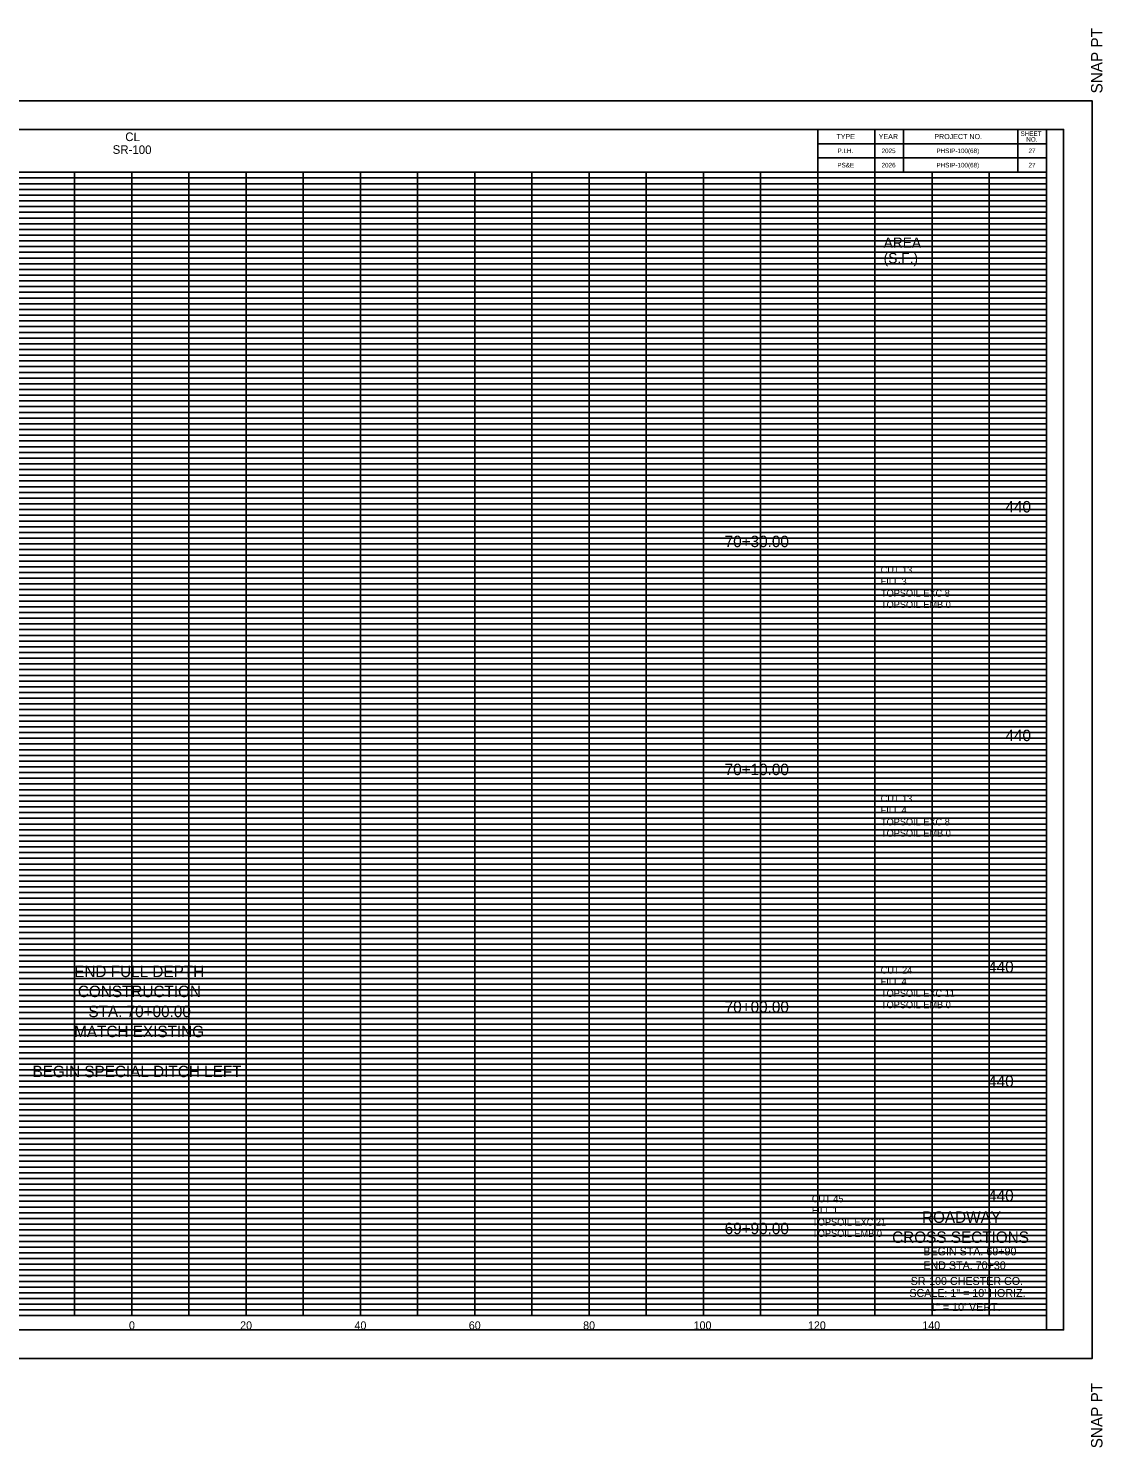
# Model space of a CAD drawing. Extents: x 37 to 1710, y 707 to 2305.
# Drawn here: x 1521.9 to 1709.8, y 1516.9 to 1765.2 of the extents above; entities that cross this region are included whole.
import ezdxf

# ---------------------------------------------------------------- set-up
doc = ezdxf.new("R2010")
doc.units = 0
for name, color, linetype in [('DESIGN - DRAINAGE - Special Ditch Width Text', 7, 'Continuous'), ('DESIGN - SCRATCH - User 1', 7, 'Continuous'), ('DESIGN - SHEET - Corner Text', 7, 'Continuous'), ('DESIGN - SHEET - Light Grid', 7, 'Continuous'), ('DESIGN - SHEET - Linework', 7, 'Continuous'), ('DESIGN - SHEET - Plot Shape', 7, 'Continuous'), ('DESIGN - TYPICAL - Text', 7, 'Continuous')]:
    doc.layers.add(name, color=color, linetype=linetype)

msp = doc.modelspace()

# ---------------------------------------------------------------- linework, layer by layer
at = {"layer": 'DESIGN - SCRATCH - User 1'}
for p, q in [((1665, 1743.75), (1665, 1743.75)), ((1672.5, 1743.75), (1672.5, 1743.75)), ((1685, 1743.75), (1685, 1743.75)), ((1697.5, 1743.75), (1697.5, 1743.75)), ((1665, 1741.25), (1665, 1741.25)), ((1672.5, 1741.25), (1672.5, 1741.25)), ((1685, 1741.25), (1685, 1741.25)), ((1697.5, 1741.25), (1697.5, 1741.25))]:
    msp.add_line(p, q, dxfattribs=at)
at = {"layer": 'DESIGN - SHEET - Light Grid'}
for p, q in [((1380, 1739), (1700, 1739)), ((1380, 1738), (1700, 1738)), ((1380, 1737), (1700, 1737)), ((1380, 1736), (1700, 1736)), ((1380, 1735), (1700, 1735)), ((1380, 1734), (1700, 1734)), ((1380, 1733), (1700, 1733)), ((1380, 1732), (1700, 1732)), ((1380, 1731), (1700, 1731)), ((1380, 1729), (1700, 1729)), ((1380, 1728), (1700, 1728)), ((1380, 1727), (1700, 1727)), ((1380, 1726), (1700, 1726)), ((1380, 1725), (1700, 1725)), ((1380, 1724), (1700, 1724)), ((1380, 1723), (1700, 1723)), ((1380, 1722), (1700, 1722)), ((1380, 1721), (1700, 1721)), ((1380, 1719), (1700, 1719)), ((1380, 1718), (1700, 1718)), ((1380, 1717), (1700, 1717)), ((1380, 1716), (1700, 1716)), ((1380, 1715), (1700, 1715)), ((1380, 1714), (1700, 1714)), ((1380, 1713), (1700, 1713)), ((1380, 1712), (1700, 1712)), ((1380, 1711), (1700, 1711)), ((1380, 1709), (1700, 1709)), ((1380, 1708), (1700, 1708)), ((1380, 1707), (1700, 1707)), ((1380, 1706), (1700, 1706)), ((1380, 1705), (1700, 1705)), ((1380, 1704), (1700, 1704)), ((1380, 1703), (1700, 1703)), ((1380, 1702), (1700, 1702)), ((1380, 1701), (1700, 1701)), ((1380, 1699), (1700, 1699)), ((1380, 1698), (1700, 1698)), ((1380, 1697), (1700, 1697)), ((1380, 1696), (1700, 1696)), ((1380, 1695), (1700, 1695)), ((1380, 1694), (1700, 1694)), ((1380, 1693), (1700, 1693)), ((1380, 1692), (1700, 1692)), ((1380, 1691), (1700, 1691)), ((1380, 1689), (1700, 1689)), ((1380, 1688), (1700, 1688)), ((1380, 1687), (1700, 1687)), ((1380, 1686), (1700, 1686)), ((1380, 1685), (1700, 1685)), ((1380, 1684), (1700, 1684)), ((1380, 1683), (1700, 1683)), ((1380, 1682), (1700, 1682)), ((1380, 1681), (1700, 1681)), ((1380, 1679), (1700, 1679)), ((1380, 1678), (1700, 1678)), ((1380, 1677), (1700, 1677)), ((1380, 1676), (1700, 1676)), ((1380, 1675), (1700, 1675)), ((1380, 1674), (1700, 1674)), ((1380, 1673), (1700, 1673)), ((1380, 1672), (1700, 1672)), ((1380, 1671), (1700, 1671)), ((1380, 1669), (1700, 1669)), ((1380, 1668), (1700, 1668)), ((1380, 1667), (1700, 1667)), ((1380, 1666), (1700, 1666)), ((1380, 1665), (1700, 1665)), ((1380, 1664), (1700, 1664)), ((1380, 1663), (1700, 1663)), ((1380, 1662), (1700, 1662)), ((1380, 1661), (1700, 1661)), ((1380, 1659), (1700, 1659)), ((1380, 1658), (1700, 1658)), ((1380, 1657), (1700, 1657)), ((1380, 1656), (1700, 1656)), ((1380, 1655), (1700, 1655)), ((1380, 1654), (1700, 1654)), ((1380, 1653), (1700, 1653)), ((1380, 1652), (1700, 1652)), ((1380, 1651), (1700, 1651)), ((1380, 1649), (1700, 1649)), ((1380, 1648), (1700, 1648)), ((1380, 1647), (1700, 1647)), ((1380, 1646), (1700, 1646)), ((1380, 1645), (1700, 1645)), ((1380, 1644), (1700, 1644)), ((1380, 1643), (1700, 1643)), ((1380, 1642), (1700, 1642)), ((1380, 1641), (1700, 1641)), ((1380, 1639), (1700, 1639)), ((1380, 1638), (1700, 1638)), ((1380, 1637), (1700, 1637)), ((1380, 1636), (1700, 1636)), ((1380, 1635), (1700, 1635)), ((1380, 1634), (1700, 1634)), ((1380, 1633), (1700, 1633)), ((1380, 1632), (1700, 1632)), ((1380, 1631), (1700, 1631)), ((1380, 1629), (1700, 1629)), ((1380, 1628), (1700, 1628)), ((1380, 1627), (1700, 1627)), ((1380, 1626), (1700, 1626)), ((1380, 1625), (1700, 1625)), ((1380, 1624), (1700, 1624)), ((1380, 1623), (1700, 1623)), ((1380, 1622), (1700, 1622)), ((1380, 1621), (1700, 1621)), ((1380, 1619), (1700, 1619)), ((1380, 1618), (1700, 1618)), ((1380, 1617), (1700, 1617)), ((1380, 1616), (1700, 1616)), ((1380, 1615), (1700, 1615)), ((1380, 1614), (1700, 1614)), ((1380, 1613), (1700, 1613)), ((1380, 1612), (1700, 1612)), ((1380, 1611), (1700, 1611)), ((1380, 1609), (1700, 1609)), ((1380, 1608), (1700, 1608)), ((1380, 1607), (1700, 1607)), ((1380, 1606), (1700, 1606)), ((1380, 1605), (1700, 1605)), ((1380, 1604), (1700, 1604)), ((1380, 1603), (1700, 1603)), ((1380, 1602), (1700, 1602)), ((1380, 1601), (1700, 1601)), ((1380, 1599), (1700, 1599)), ((1380, 1598), (1700, 1598)), ((1380, 1597), (1700, 1597)), ((1380, 1596), (1700, 1596)), ((1380, 1595), (1700, 1595)), ((1380, 1594), (1700, 1594)), ((1380, 1593), (1700, 1593)), ((1380, 1592), (1700, 1592)), ((1380, 1591), (1700, 1591)), ((1380, 1589), (1700, 1589)), ((1380, 1588), (1700, 1588)), ((1380, 1587), (1700, 1587)), ((1380, 1586), (1700, 1586)), ((1380, 1585), (1700, 1585)), ((1380, 1584), (1700, 1584)), ((1380, 1583), (1700, 1583)), ((1380, 1582), (1700, 1582)), ((1380, 1581), (1700, 1581)), ((1380, 1579), (1700, 1579)), ((1380, 1578), (1700, 1578)), ((1380, 1577), (1700, 1577)), ((1380, 1576), (1700, 1576)), ((1380, 1575), (1700, 1575)), ((1380, 1574), (1700, 1574)), ((1380, 1573), (1700, 1573)), ((1380, 1572), (1700, 1572)), ((1380, 1571), (1700, 1571)), ((1380, 1569), (1700, 1569)), ((1380, 1568), (1700, 1568)), ((1380, 1567), (1700, 1567)), ((1380, 1566), (1700, 1566)), ((1380, 1565), (1700, 1565)), ((1380, 1564), (1700, 1564)), ((1380, 1563), (1700, 1563)), ((1380, 1562), (1700, 1562)), ((1380, 1561), (1700, 1561)), ((1380, 1559), (1700, 1559)), ((1380, 1558), (1700, 1558)), ((1380, 1557), (1700, 1557)), ((1380, 1556), (1700, 1556)), ((1380, 1555), (1700, 1555)), ((1380, 1554), (1700, 1554)), ((1380, 1553), (1700, 1553)), ((1380, 1552), (1700, 1552)), ((1380, 1551), (1700, 1551)), ((1380, 1549), (1700, 1549)), ((1380, 1548), (1700, 1548)), ((1380, 1547), (1700, 1547)), ((1380, 1546), (1700, 1546)), ((1380, 1545), (1700, 1545)), ((1380, 1544), (1700, 1544)), ((1380, 1543), (1700, 1543)), ((1380, 1542), (1700, 1542)), ((1380, 1541), (1700, 1541))]:
    msp.add_line(p, q, dxfattribs=at)
at = {"layer": 'DESIGN - SHEET - Linework'}
for p, q in [((1700, 1747.5), (1660, 1747.5)), ((1660, 1740), (1660, 1747.5)), ((1670, 1740), (1670, 1747.5)), ((1675, 1740), (1675, 1747.5)), ((1695, 1740), (1695, 1747.5)), ((1700, 1740), (1700, 1747.5)), ((1700, 1745), (1660, 1745)), ((1700, 1742.5), (1660, 1742.5)), ((1380, 1740), (1700, 1740)), ((1530, 1540), (1530, 1740)), ((1540, 1540), (1540, 1740)), ((1550, 1540), (1550, 1740)), ((1560, 1540), (1560, 1740)), ((1570, 1540), (1570, 1740)), ((1580, 1540), (1580, 1740)), ((1590, 1540), (1590, 1740)), ((1600, 1540), (1600, 1740)), ((1610, 1540), (1610, 1740)), ((1620, 1540), (1620, 1740)), ((1630, 1540), (1630, 1740)), ((1640, 1540), (1640, 1740)), ((1650, 1540), (1650, 1740)), ((1660, 1540), (1660, 1740)), ((1670, 1540), (1670, 1740)), ((1680, 1540), (1680, 1740)), ((1690, 1540), (1690, 1740)), ((1380, 1730), (1700, 1730)), ((1380, 1720), (1700, 1720)), ((1380, 1710), (1700, 1710)), ((1380, 1700), (1700, 1700)), ((1380, 1690), (1700, 1690)), ((1380, 1680), (1700, 1680)), ((1380, 1670), (1700, 1670)), ((1380, 1660), (1700, 1660)), ((1380, 1650), (1700, 1650)), ((1380, 1640), (1700, 1640)), ((1380, 1630), (1700, 1630)), ((1380, 1620), (1700, 1620)), ((1380, 1610), (1700, 1610)), ((1380, 1600), (1700, 1600)), ((1380, 1590), (1700, 1590)), ((1380, 1580), (1700, 1580)), ((1380, 1570), (1700, 1570)), ((1380, 1560), (1700, 1560)), ((1380, 1550), (1700, 1550)), ((1380, 1540), (1700, 1540))]:
    msp.add_line(p, q, dxfattribs=at)
for points in [[(1368, 1752.5), (1708, 1752.5), (1708, 1532.5), (1368, 1532.5)], [(1380, 1747.5), (1700, 1747.5), (1700, 1537.5), (1380, 1537.5)]]:
    msp.add_lwpolyline(points, close=True, dxfattribs=at)
at = {"layer": 'DESIGN - SHEET - Plot Shape'}
msp.add_lwpolyline([(1373, 1747.5), (1703, 1747.5), (1703, 1537.5), (1373, 1537.5)], close=True, dxfattribs=at)

# ---------------------------------------------------------------- texts
at = {"layer": 'DESIGN - DRAINAGE - Special Ditch Width Text'}
for s, p in [('CL', (1538.85, 1745.46)), ('SR-100', (1536.64, 1743.23))]:
    msp.add_text(s, height=1.5, rotation=359.6675, dxfattribs=at).set_placement(p)
at = {"layer": 'DESIGN - SHEET - Corner Text'}
for s, p in [('  SNAP PT', (1709.8, 1752.3)), ('SNAP PT  ', (1709.8, 1516.8))]:
    msp.add_text(s, height=2, rotation=90, dxfattribs=at).set_placement(p)
for s, height, p in [('P.I.H.', 0.8, (1663.45, 1743.35)), ('2025', 0.8, (1671.16, 1743.35)), ('PHSIP-100(68)', 0.8, (1680.75, 1743.35)), ('27', 0.8, (1696.86, 1743.35)), ('PS&E', 0.8, (1663.42, 1740.85)), ('2026', 0.8, (1671.16, 1740.85)), ('PHSIP-100(68)', 0.8, (1680.75, 1740.85)), ('27', 0.8, (1696.86, 1740.85)), ('ROADWAY ', 2, (1678.23, 1556.23)), ('CROSS SECTIONS', 2, (1673.01, 1552.73)), ('BEGIN STA. 69+90', 1.4, (1678.47, 1550.55)), ('END STA. 70+30', 1.4, (1678.47, 1548.1)), ('SR-100 CHESTER CO.', 1.4, (1676.25, 1545.37)), ('SCALE: 1" = 10\' HORIZ.', 1.4, (1676.02, 1543.26)), ('       1" = 10\' VERT.   ', 1.4, (1676.02, 1540.81))]:
    msp.add_text(s, height=height, dxfattribs=at).set_placement(p)
at = {"layer": 'DESIGN - SHEET - Light Grid'}
for s, height, p in [('TYPE', 0.9, (1663.26, 1745.8)), ('YEAR', 0.9, (1670.66, 1745.8)), ('PROJECT NO.', 0.9, (1680.38, 1745.8)), ('SHEET', 0.8, (1695.47, 1746.35)), ('NO.', 0.8, (1696.47, 1745.35))]:
    msp.add_text(s, height=height, dxfattribs=at).set_placement(p)
at = {"layer": 'DESIGN - TYPICAL - Text'}
for s, height, p in [('AREA ', 1.8, (1671.52, 1726.79)), ('(S.F.)', 1.8, (1671.52, 1724.09)), ('440', 2, (1692.84, 1680.5)), ('     70+30.00     ', 2, (1640, 1674.43)), ('CUT 13', 1.2, (1671, 1669.84)), ('FILL 3', 1.2, (1671, 1667.84)), ('TOPSOIL EXC 8', 1.2, (1671.06, 1665.77)), ('TOPSOIL EMB 0', 1.2, (1671.06, 1663.78)), ('440', 2, (1692.84, 1640.5)), ('     70+10.00     ', 2, (1640, 1634.55)), ('CUT 13', 1.2, (1671, 1629.84)), ('FILL 4', 1.2, (1671, 1627.84)), ('TOPSOIL EXC 8', 1.2, (1671.06, 1625.77)), ('TOPSOIL EMB 0', 1.2, (1671.06, 1623.78)), ('END FULL DEPTH ', 2, (1529.93, 1599.22)), ('     440     ', 2, (1686.09, 1600)), ('CUT 24', 1.2, (1671, 1599.84)), ('FILL 4', 1.2, (1671, 1597.84)), ('CONSTRUCTION', 2, (1530.56, 1595.72)), ('TOPSOIL EXC 11', 1.2, (1671.06, 1595.77)), ('STA. 70+00.00', 2, (1532.41, 1592.22)), ('     70+00.00     ', 2, (1640, 1593.02)), ('TOPSOIL EMB 0', 1.2, (1671.06, 1593.78)), ('MATCH EXISTING', 2, (1529.91, 1588.72)), ('BEGIN SPECIAL DITCH LEFT', 2, (1522.63, 1581.72)), ('     440     ', 2, (1686.09, 1580)), ('     440     ', 2, (1686.09, 1560)), ('CUT 45', 1.2, (1658.96, 1559.84)), ('FILL 1', 1.2, (1658.96, 1557.84)), ('TOPSOIL EXC 21', 1.2, (1659.02, 1555.77)), ('     69+90.00     ', 2, (1640, 1554.25)), ('TOPSOIL EMB 0', 1.2, (1659.02, 1553.78)), ('     0     ', 1.4, (1536.9, 1537.6)), ('     0     ', 1.4, (1536.9, 1537.6)), ('     20     ', 1.4, (1556.35, 1537.6)), ('     40     ', 1.4, (1576.35, 1537.6)), ('     60     ', 1.4, (1596.35, 1537.6)), ('     80     ', 1.4, (1616.35, 1537.6)), ('     100     ', 1.4, (1635.68, 1537.6)), ('     120     ', 1.4, (1655.68, 1537.6)), ('     140     ', 1.4, (1675.68, 1537.6))]:
    msp.add_text(s, height=height, dxfattribs=at).set_placement(p)

doc.saveas('drawing.dxf')
